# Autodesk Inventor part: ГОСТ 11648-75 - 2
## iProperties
Created: 2006-04
Part Number: ГОСТ 11648-75 - 2
Material: Сталь низкоуглеродистая
Description: Шайба стопорная
Vendor: Autodesk Inc.
Document SubType Name: Modeling
Standard: ГОСТ 11648-75
Designer: Калинин
Standards Organization: GOST
Language: ru-RU
Size Designation: 2
Categories: <MemberInstance Version="R10.0.0"><Categories><Category DisplayName="Детали вала" InternalName="7f7aeb1f-a693-4053-b835-cee3144e0d98" Mnemonic="SHFT"><Category
Author: Калинин
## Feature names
1. Базовый элемент [Extrusion]
